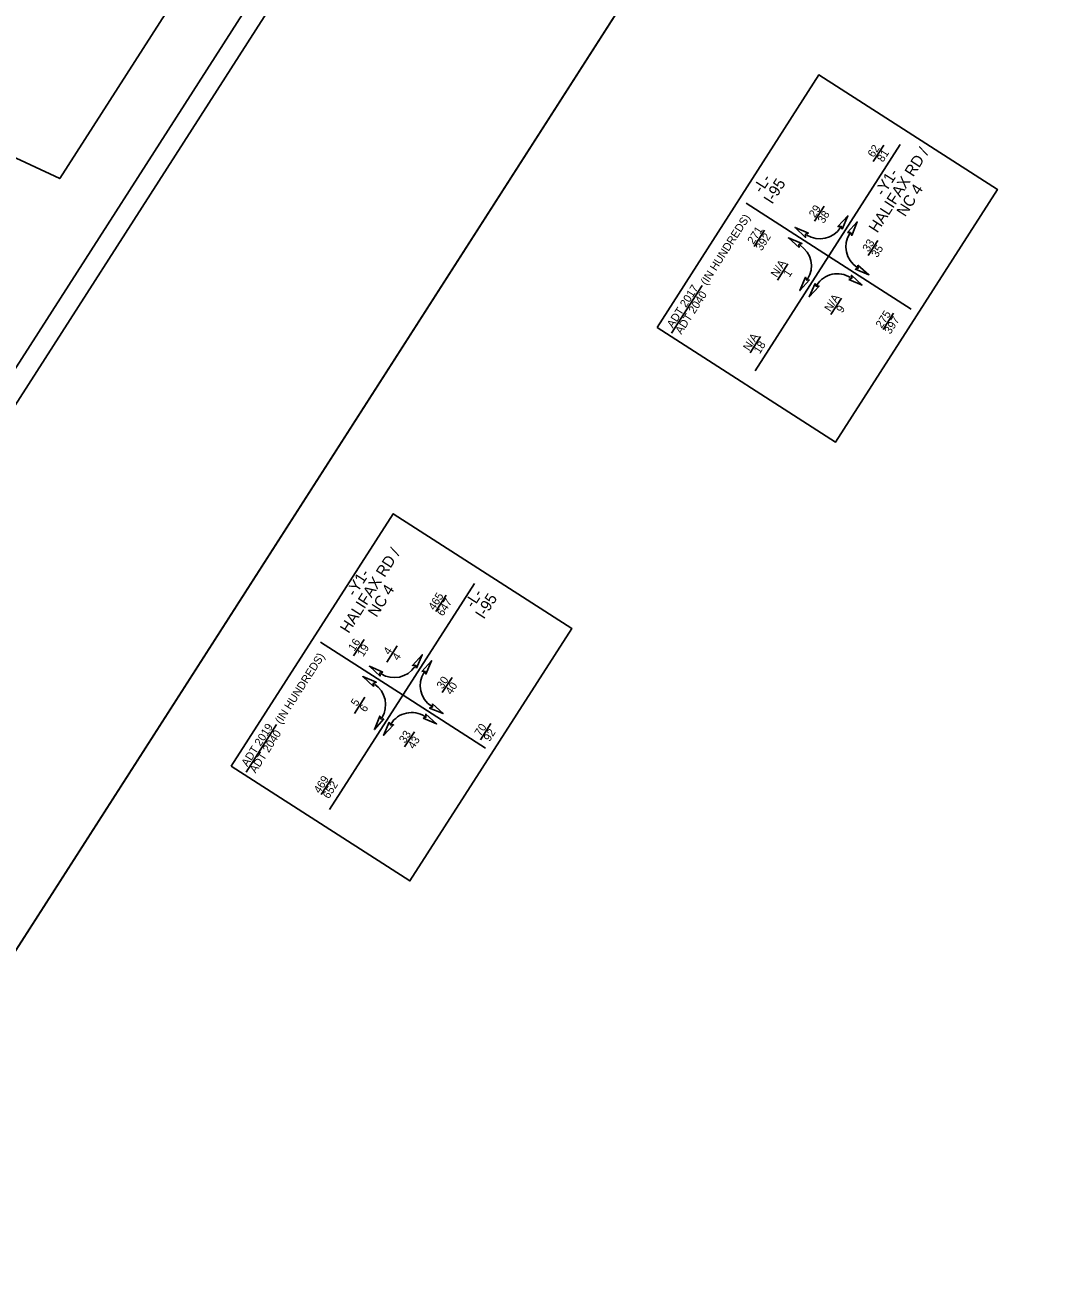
# Model space of a CAD drawing. Extents: x 2346049 to 2349719, y 842061 to 846435.
# Drawn here: x 2348821 to 2349719, y 843342 to 844432 of the extents above; entities that cross this region are included whole.
import ezdxf

# ---------------------------------------------------------------- set-up
doc = ezdxf.new("R2010")
doc.units = 0
for name, color, linetype in [('Default', 7, 'Continuous'), ('Prop DSN Text', 7, 'Continuous'), ('Scratch_Level_0', 7, 'Continuous'), ('Sheet Cutting Line CELL', 7, 'Continuous'), ('Sheet Detail CELL', 7, 'Continuous'), ('Sheet Plot Border Inside CELL', 7, 'Continuous'), ('Sheet Plot Border Outside CELL', 7, 'Continuous')]:
    doc.layers.add(name, color=color, linetype=linetype)

msp = doc.modelspace()

# ---------------------------------------------------------------- linework, layer by layer
at = {"layer": 'Default'}
for points in [[(2349536.7, 844252.9), (2349541.7, 844264.5), (2349533, 844255.2), (2349535.8, 844255.3)], [(2349507.1, 844249.4), (2349495.4, 844254.4), (2349504.7, 844245.7), (2349504.6, 844248.5)], [(2349541.4, 844249.9), (2349549.8, 844259.3), (2349545, 844247.5), (2349543.9, 844250.1)], [(2349499, 844236.9), (2349489.6, 844245.3), (2349501.4, 844240.5), (2349498.8, 844239.5)], [(2349550.5, 844221.5), (2349560, 844213), (2349548.2, 844217.9), (2349550.8, 844218.9)], [(2349508.2, 844208.5), (2349499.7, 844199.1), (2349504.6, 844210.8), (2349505.6, 844208.3)], [(2349542.5, 844209), (2349554.1, 844204), (2349544.8, 844212.6), (2349545, 844209.9)], [(2349512.9, 844205.5), (2349507.9, 844193.8), (2349516.5, 844203.1), (2349513.8, 844203)], [(2349164.1, 843869), (2349169.1, 843880.6), (2349160.5, 843871.3), (2349163.2, 843871.4)], [(2349134.5, 843865.5), (2349122.9, 843870.5), (2349132.2, 843861.9), (2349132, 843864.6)], [(2349168.8, 843866), (2349177.3, 843875.4), (2349172.4, 843863.7), (2349171.4, 843866.2)], [(2349126.5, 843853), (2349117, 843861.5), (2349128.8, 843856.6), (2349126.2, 843855.6)], [(2349178, 843837.6), (2349187.4, 843829.1), (2349175.6, 843834), (2349178.2, 843835)], [(2349135.6, 843824.6), (2349127.2, 843815.2), (2349132, 843827), (2349133.1, 843824.4)], [(2349169.9, 843825.1), (2349181.6, 843820.1), (2349172.3, 843828.8), (2349172.4, 843826)], [(2349140.3, 843821.6), (2349135.3, 843810), (2349144, 843819.3), (2349141.2, 843819.2)]]:
    msp.add_lwpolyline(points, close=True, dxfattribs=at)
for centre, start, end in [((2349517.2, 844265.8), 237.3281, 327.3281), ((2349488.3, 844220.8), 327.3282, 57.3282), ((2349561.3, 844237.5), 147.3282, 237.3282), ((2349532.4, 844192.5), 57.3281, 147.3281), ((2349144.6, 843882), 237.3281, 327.3281), ((2349188.7, 843853.7), 147.3282, 237.3282), ((2349115.7, 843836.9), 327.3282, 57.3282), ((2349159.8, 843808.7), 57.3281, 147.3281)]:
    msp.add_arc(centre, 21.4, start, end, dxfattribs=at)
at = {"layer": 'Prop DSN Text'}
for p, q in [((2349460.6, 844129.1), (2349587.4, 844326.9)), ((2349563.9, 844312), (2349573, 844326.4)), ((2349452.5, 844275.6), (2349524.8, 844229.3)), ((2349512.5, 844259.8), (2349521, 844273)), ((2349459.6, 844237.6), (2349468.8, 844251.9)), ((2349559.3, 844229.8), (2349567.8, 844243)), ((2349524.8, 844229.3), (2349597.1, 844182.9)), ((2349480, 844208.2), (2349489.1, 844222.6)), ((2349387.4, 844161.9), (2349414.1, 844203.5)), ((2349526.8, 844178.2), (2349536, 844192.5)), ((2349572.5, 844165.2), (2349581.7, 844179.5)), ((2349456.1, 844144.7), (2349465.3, 844159)), ((2349088, 843745.2), (2349214.9, 843943)), ((2349180.9, 843918.4), (2349190.1, 843932.7)), ((2349080, 843891.7), (2349152.3, 843845.4)), ((2349109, 843879.7), (2349118.2, 843894)), ((2349138.2, 843874), (2349147.3, 843888.3)), ((2349186.7, 843847.5), (2349195.2, 843860.7)), ((2349109.7, 843829.1), (2349118.9, 843843.4)), ((2349152.3, 843845.4), (2349224.6, 843799)), ((2349014.9, 843778), (2349041.5, 843819.6)), ((2349220, 843806.1), (2349229.2, 843820.4)), ((2349153.7, 843800), (2349162.2, 843813.2)), ((2349080.7, 843758.3), (2349089.9, 843772.6))]:
    msp.add_line(p, q, dxfattribs=at)
for points in [[(2349374.6, 844167), (2349516.2, 844387.8), (2349672.5, 844287.6), (2349530.9, 844066.7)], [(2349002, 843783.1), (2349143.7, 844003.9), (2349300, 843903.7), (2349158.3, 843682.8)]]:
    msp.add_lwpolyline(points, close=True, dxfattribs=at)
at = {"layer": 'Scratch_Level_0'}
for points in [[(2349350.4, 845074.8), (2348851.8, 844297.2), (2348757.8, 844341), (2348462.4, 843706.5), (2348375.3, 843541.3), (2348255.5, 843353.8), (2348231.9, 843354.7), (2348207.8, 843279), (2348000.9, 842955.2), (2347829, 843060.7), (2347638.3, 842833.8), (2347080.7, 843191.4), (2347008.6, 843443.9), (2347324.8, 843936.9), (2346937.8, 844263.6), (2347160.2, 844610.4)], [(2349350.4, 845074.8), (2348851.8, 844297.2), (2348757.8, 844341), (2348462.4, 843706.5), (2348375.3, 843541.3), (2348255.5, 843353.8), (2348231.9, 843354.7), (2348207.8, 843279), (2348000.9, 842955.2), (2347829, 843060.7), (2347638.3, 842833.8), (2347080.7, 843191.4), (2347008.6, 843443.9), (2347324.8, 843936.9), (2346961.1, 844244), (2347005, 844312.5), (2347188.2, 844598.2)], [(2349350.4, 845074.8), (2348851.8, 844297.2), (2348757.8, 844341), (2348462.4, 843706.5), (2348375.3, 843541.3), (2348255.5, 843353.8), (2348231.9, 843354.7), (2348207.8, 843279), (2348000.9, 842955.2), (2347829, 843060.7), (2347638.3, 842833.8), (2347080.7, 843191.4), (2347008.6, 843443.9), (2347324.8, 843936.9), (2346961.1, 844244), (2347005, 844312.5), (2347188.2, 844598.2)]]:
    msp.add_lwpolyline(points, dxfattribs=at)
at = {"layer": 'Sheet Cutting Line CELL'}
msp.add_line((2347900.5, 842198.8), (2349718.7, 845033.9), dxfattribs=at)
msp.add_line((2347900.5, 842198.8), (2349718.7, 845033.9), dxfattribs=at)
at = {"layer": 'Sheet Detail CELL'}
msp.add_lwpolyline([(2346465.3, 843526.7), (2348084.7, 846052), (2349473.7, 845161.3), (2347854.2, 842636)], close=True, dxfattribs=at)
at = {"layer": 'Sheet Plot Border Inside CELL'}
msp.add_lwpolyline([(2348083.9, 846082.3), (2346302.5, 843304.4), (2347720, 842395.3), (2349501.5, 845173.2)], close=True, dxfattribs=at)
at = {"layer": 'Sheet Plot Border Outside CELL'}
msp.add_lwpolyline([(2347866.8, 846221.5), (2346048.7, 843386.4), (2347900.5, 842198.8), (2349718.7, 845033.9)], close=True, dxfattribs=at)

# ---------------------------------------------------------------- texts
at = {"layer": 'Prop DSN Text'}
for s, height, p in [('62', 7, (2349564.2, 844315.1)), ('HALIFAX RD / ', 9.8, (2349567.4, 844249)), ('81', 7, (2349572.4, 844311)), ('-Y1-', 9.8, (2349572.9, 844281.2)), ('-L-', 9.8, (2349466.3, 844283.7)), ('I-95', 9.8, (2349475.4, 844274.1)), ('NC 4', 9.8, (2349591.8, 844263.1)), ('29', 7, (2349512.8, 844262.4)), ('(IN HUNDREDS)', 7, (2349418.1, 844203.2)), ('38', 7, (2349520.5, 844257.4)), ('271', 7, (2349459, 844239.2)), ('392', 7, (2349466.2, 844233.4)), ('33', 7, (2349559.7, 844232.5)), ('35', 7, (2349567.4, 844227.5)), ('N/A', 7, (2349479.5, 844210.1)), ('1', 7, (2349490.5, 844210.3)), ('ADT 2017', 7, (2349388.5, 844165.9)), ('ADT 2040', 7, (2349395.9, 844160.4)), ('N/A', 7, (2349526.4, 844180.1)), ('9', 7, (2349536.7, 844179.1)), ('275', 7, (2349571.3, 844165.7)), ('397', 7, (2349578.8, 844160.5)), ('N/A', 7, (2349455.3, 844145.9)), ('18', 7, (2349464.5, 844143.3)), ('HALIFAX RD / ', 9.8, (2349104.7, 843898.7)), ('-Y1-', 9.8, (2349110.2, 843930.9)), ('NC 4', 9.8, (2349129.1, 843912.8)), ('465', 7, (2349179.7, 843919)), ('-L-', 9.8, (2349213.9, 843920.8)), ('I-95', 9.8, (2349223, 843911.2)), ('647', 7, (2349187.2, 843913.8)), ('16', 7, (2349109.7, 843883.2)), ('(IN HUNDREDS)', 7, (2349045.6, 843819.4)), ('19', 7, (2349117.4, 843878.3)), ('4', 7, (2349140.4, 843880)), ('4', 7, (2349148.1, 843875)), ('30', 7, (2349187, 843850.1)), ('40', 7, (2349194.7, 843845.1)), ('5', 7, (2349111.9, 843835)), ('6', 7, (2349119.5, 843829.9)), ('ADT 2019', 7, (2349016.1, 843782.2)), ('ADT 2040', 7, (2349023.3, 843776.5)), ('33', 7, (2349154.1, 843802.7)), ('70', 7, (2349220.2, 843808.8)), ('92', 7, (2349228.1, 843804.2)), ('43', 7, (2349161.8, 843797.7)), ('469', 7, (2349079.4, 843758.8)), ('652', 7, (2349087.3, 843754.1))]:
    msp.add_text(s, height=height, rotation=57.3281, dxfattribs=at).set_placement(p)

doc.saveas('drawing.dxf')
